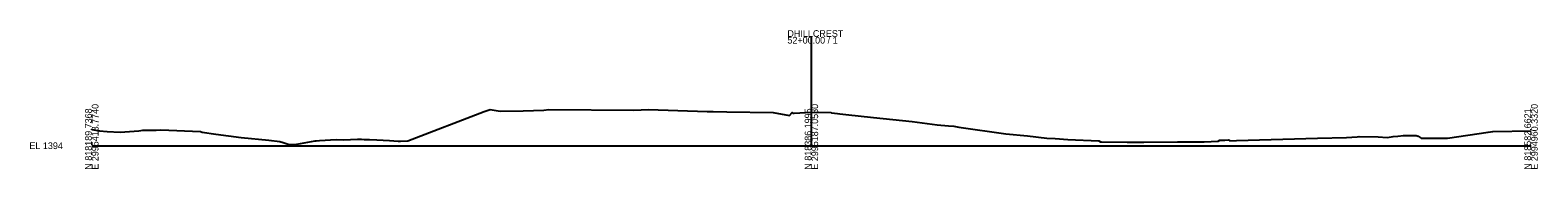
# Model space of a CAD drawing. Extents: x -26 to 603, y -10 to 2564.
# Drawn here: x -26 to 603, y 1990 to 2048 of the extents above; entities that cross this region are included whole.
import ezdxf

# ---------------------------------------------------------------- set-up
doc = ezdxf.new("R2010")
doc.units = 0
doc.layers.add('DESIGN - SHEET - Light Grid', color=7, linetype='Continuous')
doc.layers.add('SURVEY - GROUND - Top of Ground', color=7, linetype='Continuous')

msp = doc.modelspace()

# ---------------------------------------------------------------- linework, layer by layer
at = {"layer": 'DESIGN - SHEET - Light Grid'}
for p, q in [((300, 2000), (300, 2045.5)), ((0, 2000), (300, 2000)), ((300, 2000), (600, 2000))]:
    msp.add_line(p, q, dxfattribs=at)
at = {"layer": 'SURVEY - GROUND - Top of Ground'}
msp.add_lwpolyline([(0, 2006.83), (3.19, 2006.18), (6.39, 2005.95), (11.78, 2005.63), (19.67, 2006.25), (21.3, 2006.52), (25.42, 2006.5), (26.84, 2006.51), (28.84, 2006.61), (45.3, 2005.99), (46.05, 2005.73), (51.65, 2004.88), (62.24, 2003.43), (73.8, 2002.37), (78.34, 2001.83), (79.78, 2001.36), (81.82, 2000.63), (82.89, 2000.55), (85.42, 2000.64), (93.14, 2001.98), (93.61, 2002.04), (94.89, 2002.14), (101.84, 2002.55), (104.92, 2002.51), (110.83, 2002.75), (112.47, 2002.7), (113.57, 2002.66), (115.77, 2002.59), (118.85, 2002.45), (124.16, 2002.13), (127.69, 2001.92), (128.69, 2001.91), (131.72, 2002.08), (163.63, 2014.26), (166.08, 2015.17), (170.29, 2014.45), (179.84, 2014.59), (188.51, 2014.87), (190.59, 2015.12), (225.97, 2014.92), (232.04, 2015.16), (256.54, 2014.37), (259.05, 2014.31), (264.72, 2014.19), (284.01, 2013.84), (290.8, 2012.62), (291.92, 2013.87), (292.27, 2013.6), (292.88, 2013.63), (299.9, 2014.06), (308.17, 2013.85), (308.31, 2013.81), (310.92, 2013.47), (311.81, 2013.36), (314.39, 2013.03), (325.91, 2011.78), (341.96, 2010.1), (352.49, 2008.76), (357.22, 2008.35), (359.33, 2008.14), (361.48, 2007.81), (381.05, 2004.98), (390.13, 2004.14), (398.13, 2003.22), (401.57, 2002.96), (406.86, 2002.62), (419.81, 2002.03), (420.45, 2001.65), (420.95, 2001.64), (431.57, 2001.49), (438.59, 2001.48), (452.6, 2001.57), (463.76, 2001.63), (469.57, 2001.86), (470.2, 2002.26), (472.34, 2002.36), (473.82, 2002.46), (474.48, 2002.1), (477.22, 2002.18), (510.92, 2003.18), (523.1, 2003.48), (527.46, 2003.68), (528.4, 2003.88), (536.23, 2003.73), (540.04, 2003.46), (542.54, 2003.81), (544.5, 2003.98), (546.81, 2004.3), (552.17, 2004.26), (552.98, 2003.95), (554.21, 2003.13), (562.7, 2003.13), (565.21, 2003.1), (582.07, 2005.7), (584.12, 2005.96), (600, 2006.17)], dxfattribs=at)

# ---------------------------------------------------------------- texts
at = {"layer": 'DESIGN - SHEET - Light Grid'}
for s, p in [('52+00.00 / 1', (290, 2042.7)), ('DHILLCREST', (290, 2045.5)), ('EL 1394', (-26, 1998.6))]:
    msp.add_text(s, height=2.8, dxfattribs=at).set_placement(p)
for s, p in [('N 818189.7368', (0, 1990)), ('E 2995413.7740', (2.8, 1990)), ('N 818386.1995', (300, 1990)), ('E 2995187.0530', (302.8, 1990)), ('N 818582.6621', (600, 1990)), ('E 2994960.3320', (602.8, 1990))]:
    msp.add_text(s, height=2.8, rotation=90, dxfattribs=at).set_placement(p)

doc.saveas('drawing.dxf')
